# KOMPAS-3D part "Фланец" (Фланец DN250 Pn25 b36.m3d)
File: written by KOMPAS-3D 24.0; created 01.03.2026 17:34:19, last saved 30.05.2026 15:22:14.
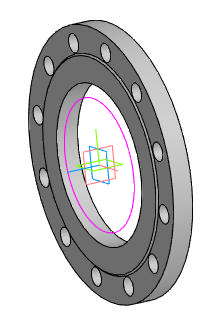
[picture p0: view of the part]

Document properties: Автор: R2D2; Полное имя файла: E:\Работа\Зайцев\GVWR2434M-2W-F-ОСТ Задвижка клиновая с выдвижным штоком DN.ru Ду50-300 Ру25\исходные материалы\DN250\Фланец DN250 Pn25 b36.m3d

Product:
- Part/product: Фланец
    Масса: 22.773233
    additional columns: Типовые

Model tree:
1. Эскиз:2
2. Элемент вращения:1
     Угол 1 = 360
3. Эскиз:3  (with: Грань.Элемент вращения:1)
4. Элемент выдавливания:2
     Расстояние 1 = 3; Расстояние 2 = 33
5. Массив по концентрической сетке:1  (with: Элемент выдавливания:2, Эскиз:3, Грань.Элемент вращения:1)  (12 pattern instances)
     Шаг 2 = 360
6. Эскиз:4  (with: Грань.Элемент вращения:1)
7. Элемент выдавливания:3
     Расстояние 2 = 4

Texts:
  Линейный размер с обрывом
